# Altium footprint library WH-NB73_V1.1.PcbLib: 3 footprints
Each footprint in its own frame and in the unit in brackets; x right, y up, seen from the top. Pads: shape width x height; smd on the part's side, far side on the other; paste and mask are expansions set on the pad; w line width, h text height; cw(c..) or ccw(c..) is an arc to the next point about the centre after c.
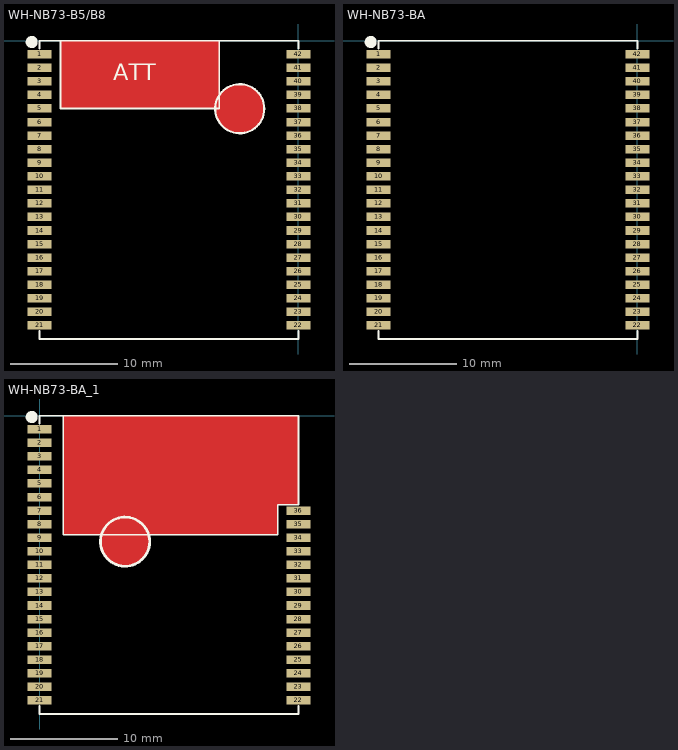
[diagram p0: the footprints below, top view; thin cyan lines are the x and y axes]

## WH-NB73-B5/B8 [mm]
pads (42):
  rect 2.25x0.8 smd: 1(-24.25,-1.27) 2(-24.25,-2.54) 3(-24.25,-3.81) 4(-24.25,-5.08) 5(-24.25,-6.35) 6(-24.25,-7.62) 7(-24.25,-8.89) 8(-24.25,-10.16) 9(-24.25,-11.43) 10(-24.25,-12.7) 11(-24.25,-13.97) 12(-24.25,-15.24) 13(-24.25,-16.51) 14(-24.25,-17.78) 15(-24.25,-19.05) 16(-24.25,-20.32) 17(-24.25,-21.59) 18(-24.25,-22.86) 19(-24.25,-24.13) 20(-24.25,-25.4) 21(-24.25,-26.67) 22(0,-26.67) 23(0,-25.4) 24(0,-24.13) 25(0,-22.86) 26(0,-21.59) 27(0,-20.32) 28(0,-19.05) 29(0,-17.78) 30(0,-16.51) 31(0,-15.24) 32(0,-13.97) 33(0,-12.7) 34(0,-11.43) 35(0,-10.16) 36(0,-8.89) 37(0,-7.62) 38(0,-6.35) 39(0,-5.08) 40(0,-3.81) 41(0,-2.54) 42(0,-1.27)
Top Layer:
  pour cut-out: -22.285,-6.35 -22.285,0 -7.426,0 -7.426,-6.35
  pour cut-out: -3.189,-6.375 -3.233,-5.923 -3.365,-5.489 -3.579,-5.088 -3.867,-4.737 -4.218,-4.449 -4.619,-4.235 -5.053,-4.103 -5.505,-4.059 -5.505,-4.07 -5.55,-4.059 -5.99,-4.102 -6.414,-4.231 -6.804,-4.439 -7.146,-4.72 -7.427,-5.062 -7.635,-5.452 -7.764,-5.876 -7.807,-6.316 -7.796,-6.316 -7.807,-6.37 -7.762,-6.825 -7.63,-7.262 -7.414,-7.665 -7.124,-8.018 -6.771,-8.308 -6.368,-8.524 -5.931,-8.656 -5.476,-8.701 -5.476,-8.69 -5.46,-8.701 -5.017,-8.657 -4.591,-8.528 -4.198,-8.318 -3.854,-8.036 -3.572,-7.692 -3.362,-7.299 -3.233,-6.873 -3.189,-6.43 -3.2,-6.43
Top Overlay:
  circle w0.559: c-24.987,-0.127 r0.284
  circle w0.2: c-5.5,-6.375 r2.3
  lines w0.152: -24.25,-27.178 -24.25,-27.94 0,-27.94 0,-27.178 ; -24.25,-0.762 -24.25,0 0,0 0,-0.762 ; -22.285,-2.54 -22.285,-6.35 -10.412,-6.35 -7.426,-6.35 -7.426,-5.08 -7.426,0 ; -22.285,-2.508 -22.285,0
  text "ATT" at -17.332,-3.683 h1.52

## WH-NB73-BA [mm] "EXTERNAL ANTENNA"
pads (42):
  rect 2.25x0.8 smd: 1(-24.25,-1.27) 2(-24.25,-2.54) 3(-24.25,-3.81) 4(-24.25,-5.08) 5(-24.25,-6.35) 6(-24.25,-7.62) 7(-24.25,-8.89) 8(-24.25,-10.16) 9(-24.25,-11.43) 10(-24.25,-12.7) 11(-24.25,-13.97) 12(-24.25,-15.24) 13(-24.25,-16.51) 14(-24.25,-17.78) 15(-24.25,-19.05) 16(-24.25,-20.32) 17(-24.25,-21.59) 18(-24.25,-22.86) 19(-24.25,-24.13) 20(-24.25,-25.4) 21(-24.25,-26.67) 22(0,-26.67) 23(0,-25.4) 24(0,-24.13) 25(0,-22.86) 26(0,-21.59) 27(0,-20.32) 28(0,-19.05) 29(0,-17.78) 30(0,-16.51) 31(0,-15.24) 32(0,-13.97) 33(0,-12.7) 34(0,-11.43) 35(0,-10.16) 36(0,-8.89) 37(0,-7.62) 38(0,-6.35) 39(0,-5.08) 40(0,-3.81) 41(0,-2.54) 42(0,-1.27)
Top Overlay:
  circle w0.559: c-24.987,-0.127 r0.284
  lines w0.152: -24.25,-27.178 -24.25,-27.94 0,-27.94 0,-27.178 ; -24.25,-0.762 -24.25,0 0,0 0,-0.762

## WH-NB73-BA_1 [mm] "INTERNAL ANTENNA"
pads (36):
  rect 2.25x0.8 smd: 1(0,-1.27) 2(0,-2.54) 3(0,-3.81) 4(0,-5.08) 5(0,-6.35) 6(0,-7.62) 7(0,-8.89) 8(0,-10.16) 9(0,-11.43) 10(0,-12.7) 11(0,-13.97) 12(0,-15.24) 13(0,-16.51) 14(0,-17.78) 15(0,-19.05) 16(0,-20.32) 17(0,-21.59) 18(0,-22.86) 19(0,-24.13) 20(0,-25.4) 21(0,-26.67) 22(24.25,-26.67) 23(24.25,-25.4) 24(24.25,-24.13) 25(24.25,-22.86) 26(24.25,-21.59) 27(24.25,-20.32) 28(24.25,-19.05) 29(24.25,-17.78) 30(24.25,-16.51) 31(24.25,-15.24) 32(24.25,-13.97) 33(24.25,-12.7) 34(24.25,-11.43) 35(24.25,-10.16) 36(24.25,-8.89)
Top Layer:
  pour cut-out: 7.95,-9.5 8.011,-9.489 8.461,-9.533 8.895,-9.665 9.294,-9.878 9.644,-10.165 9.931,-10.515 10.144,-10.914 10.276,-11.348 10.32,-11.798 10.309,-11.798 10.32,-11.831 10.276,-12.278 10.146,-12.707 9.934,-13.103 9.649,-13.45 9.302,-13.735 8.906,-13.947 8.477,-14.077 8.03,-14.121 8.03,-14.11 7.95,-14.121 7.509,-14.077 7.085,-13.949 6.694,-13.74 6.351,-13.459 6.07,-13.116 5.861,-12.725 5.733,-12.301 5.689,-11.86 5.7,-11.86 5.89,-10.87 6.47,-10.06 7.2,-9.67
  pour cut-out: 2.209,0 2.209,-11.135 22.312,-11.135 22.312,-8.336 24.25,-8.336 24.25,0
Bottom Layer:
  pour cut-out: 2.209,0.06 2.209,-11.075 22.312,-11.075 22.312,-8.276 24.25,-8.276 24.25,0.06
  pour cut-out: 7.98,-9.46 8.041,-9.449 8.491,-9.493 8.925,-9.625 9.324,-9.838 9.674,-10.125 9.961,-10.475 10.174,-10.874 10.306,-11.308 10.35,-11.758 10.339,-11.758 10.35,-11.791 10.306,-12.238 10.176,-12.667 9.964,-13.063 9.679,-13.41 9.332,-13.695 8.936,-13.907 8.507,-14.037 8.06,-14.081 8.06,-14.07 7.98,-14.081 7.539,-14.037 7.115,-13.909 6.724,-13.7 6.381,-13.419 6.1,-13.076 5.891,-12.685 5.763,-12.261 5.719,-11.82 5.73,-11.82 5.92,-10.83 6.5,-10.02 7.23,-9.63
Top Overlay:
  circle w0.559: c-0.737,-0.127 r0.284
  circle w0.254: c8.009,-11.798 r2.3
  lines w0.152: 0,-27.178 0,-27.94 24.25,-27.94 24.25,-27.178 ; 0,-0.762 0,0 24.25,0 24.25,-8.336 22.312,-8.336 22.312,-11.135 2.209,-11.135 2.209,0 ; 24.25,-6.35 24.25,-6.34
